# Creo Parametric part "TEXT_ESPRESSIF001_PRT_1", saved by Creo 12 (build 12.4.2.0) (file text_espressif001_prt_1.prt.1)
Units: Custom; MM, KILOGRAM, SECS

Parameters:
  PTC_WM_ITERATION = "0"
  PTC_WM_VERSION = "-.0"
  PTC_WM_LIFECYCLE_STATE = "In Work"
  PTC_WM_LIFECYCLE = "MO_CADDocument"
  PTC_WM_CREATED_BY = "Maximilian Roepper (Z0017RMS: MO)"
  PTC_WM_CREATED_ON = "18-Sep-26 11:36:42 AM"
  PTC_WM_MODIFIED_BY = "Maximilian Roepper (Z0017RMS: MO)"
  PTC_WM_MODIFIED_ON = "18-Sep-26 11:36:46 AM"
  PDMLINKNUMBER = "PDM000071455031"
  PTC_WM_NAME = "text_espressif001_prt_1.prt"
  PTC_WM_NUMBER = "PDM000071455031"

Other parameters: WEIGHT, WEIGHT_FACTOR, WEIGHT_ADD, _MASS_TEMP, _DIFF_TEMP, MC_ERRORS, SUPPLIER

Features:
  1. coordinate system
  2. datum plane "PRT_YZ"
  3. datum plane "PRT_XY"
  4. datum plane "PRT_XZ"
  5. coordinate system
  6. datum axis
  7. datum axis
  8. datum axis
  9. coordinate system
  10. imported feature
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
Other named items: PRT, SIEMENS_MO, DRW_VIEW_ORG, PRT_X, PRT_Y, PRT_Z, CS0, ROUGH_GROB

Layers: 00_STD_CSYS-KSYS, 01_STD_PLANES-EBENEN, 02_STD_AXES-ACHSEN, 03_STD_CSYS-KSYS, 24_IMPORT_FEAT-IMPORT_KE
